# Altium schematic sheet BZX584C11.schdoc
size 127 x 101 mm
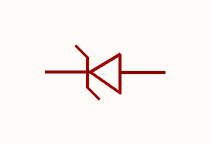
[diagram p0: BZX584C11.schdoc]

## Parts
ZD?  bzx584c11  [SOD-523F_L1.2-W0.8-LS1.7-RD]  (value not drawn)

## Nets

Not connected (* = marked no-connect by the designer): ZD? 1(K) 2(A)

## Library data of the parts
ZD? = bzx584c11: 二极管配置:1个独立式;稳压值(标称值):11V;稳压值(范围值):10.4V~11.6V;耗散功率(Pd):150mW;; Manufacturer: CJ(江苏长电/长晶); AddInBom: yes; ModelId: 1a3524270898456e95fda80dc56db1b2; ModelName: SOD-523F_L1.2-W0.8-H0.6-LS1.6; ModelTransform: 62.992,31.496,0,0,0,0,-0.005,0.16,0; Diode Configuration: 1个独立式; Zener Voltage(Nom): 11V; Reverse Leakage Current (Ir): 100nA; Pd - Power Dissipation: 150mW; Impedance(Zzt): 20Ω; Impedance(Zzk): 150Ω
